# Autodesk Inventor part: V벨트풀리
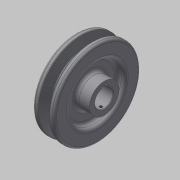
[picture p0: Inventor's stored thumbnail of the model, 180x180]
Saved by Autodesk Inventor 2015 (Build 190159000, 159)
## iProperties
Created: 2015-11
Part Number: V벨트풀리
Material: 강철, 탄소
Document SubType Name: Modeling
Designer: mduedu
Density: 1 g/cm^3
Appearance: 기본값
Author: mduedu
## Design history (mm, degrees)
sketch "스케치1"
  geometry: L1 (-9.5, 0)-(9.5, 0); L2 (0, 0)-(0, 37.7); L3 (-4.825, 37.7)-(-9.5, 37.7); L4 (-9.5, 37.7)-(-9.5, 0); L5 (0, 28.7)-(-2.074, 28.7); L6 (-2.074, 28.7)-(-4.825, 37.7); L7 (4.825, 37.7)-(9.5, 37.7); L8 (9.5, 37.7)-(9.5, 0); L9 (0, 28.7)-(2.074, 28.7); L10 (2.074, 28.7)-(4.825, 37.7); L11 (-9.5, 35)-(9.5, 35); 3 further points
  constraints: 22 end point, 7 point on line, 4 perpendicular, 3 symmetric about line, 1 coincident, 1 horizontal, 1 horizontal alignment, 1 midpoint, 1 vertical
  dimensions: "d0" = 19 distance of L1.start L1.end; "d2" = 75.4 diameter of L2.end L1 (derived); "d3" = 34 deg angle of L10 L6; "d4" = 6.3 distance between parallel lines of L11 L9; "d5" = 2.7 distance between parallel lines of L7 L11; "d6" = 8 distance of point (4, 35) point (-4, 35); "d7" = 70 diameter of L11 L1
revolve "회전1" sketch "스케치1" stored, may be unused: angle "d8" = 90 deg
sketch "스케치2"
  geometry: C1 r 24 at (0, 0); C2 r 13 at (0, 0); 1 further point
  constraints: 2 centre point, 2 coincident
  dimensions: "d9" = 48 diameter of C1; "d10" = 26 diameter of C2
extrude "돌출1" cut sketch "스케치2" distance "d11" = 6; taper "d12" = 0 deg
extrude "돌출3" join sketch "스케치2" distance "d37" = 6; taper "d38" = 0 deg
fillet "모깎기1" dims "d13" = 3
fillet "모깎기2" dims "d14" = 3
fillet "모깎기3" dims "d15" = 1, "d16" = 0.5, "d17" = 2
hole "구멍1" diameter "d20" = 16; stored, may be unused: countersink angle "d24" = 90 deg, drill point angle "d26" = 118 deg; dims "d21" = 6, "d22" = 4, "d23" = 2, "d25" = 8, "d53" = 10, "d54" = 10
sketch "스케치3"
  geometry: L1 (-2.5, 0)-(2.5, 0); L2 (2.5, 0)-(2.5, 10.3); L3 (2.5, 10.3)-(-2.5, 10.3); L4 (-2.5, 10.3)-(-2.5, 0); 2 further points
  constraints: 8 end point, 2 parallel, 1 coincident, 1 horizontal, 1 midpoint, 1 perpendicular
  dimensions: "d27" = 5 distance of L2.end L3.end; "d29" = 10.3 distance of L3.end L1.start
extrude "돌출2" cut sketch "스케치3" stored distance "d30" = 6; taper "d31" = 0 deg
node "작업 평면1"
sketch "스케치4"
  geometry: L1 (19, -27)-(19, 27) reference; 2 further points
  constraints: 1 horizontal alignment
  dimensions: "d52" = 22 distance from line of L1 point (-3, 0)
hole "구멍2" sketch "스케치4" at (-3, 0) diameter "d42" = 2.459; stored, may be unused: countersink angle "d46" = 90 deg, drill point angle "d48" = 118 deg; dims "d43" = 6, "d44" = 4, "d45" = 2, "d47" = 8
chamfer "모따기3" distance "d58" = 0.5; stored, may be unused: second distance "d59" = 2, angle "d60" = 45 deg
node "솔리드1"
mirror "대칭1"
